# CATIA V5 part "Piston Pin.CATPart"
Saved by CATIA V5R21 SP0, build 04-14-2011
Part number: Piston Pin
Bounding box of the stored display mesh (mm): x -11 to 11, y -10.833 to 10.833, z -40 to 40
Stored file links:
  D:\CATIA V5R21 E-RESOURCES\CATIA-V5R21\catia-v5r21-Prts\c13_catia_v5r21_prt\c13_catia_v5r21_figr_13-41\Part & Asm files\Piston Pin.CATPart
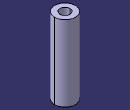
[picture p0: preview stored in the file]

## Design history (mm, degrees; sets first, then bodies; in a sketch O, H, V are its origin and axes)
Body1 (main body)
  Sketch1 on xy-plane, origin (0, 0, 0), H (1, 0, 0), V (0, 1, 0)
    circle A1 centre (0, 0) radius 5.5
    circle A2 centre (0, 0) radius 11
    point P1 (0, 0)
    radius A2 = 11
    radius A1 = 5.5
    coincidence: P1 H
    concentricity: A1 A2
  Pad1: profile Sketch1, direction (0, 0, 1), length 40, mirrored extent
